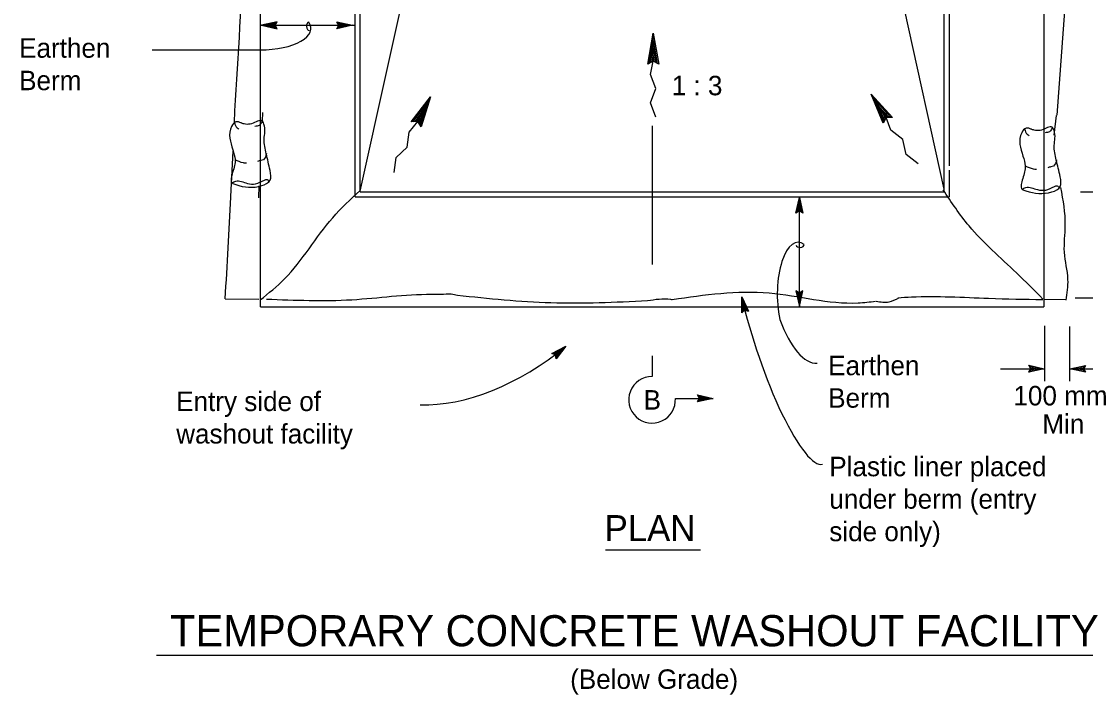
# Model space of a CAD drawing. Extents: x 6707406 to 6714471, y 1868570 to 1872341.
# Drawn here: x 6708832.1 to 6709225.4, y 1868570.1 to 1868819.1 of the extents above; entities that cross this region are included whole.
import ezdxf

# ---------------------------------------------------------------- set-up
doc = ezdxf.new("R2010")
doc.units = 0
for name, color, linetype in [('1 Control', 7, 'Continuous'), ('56 Stg 3 Anno', 7, 'Continuous'), ('57 Undefined', 7, 'Continuous'), ('60 Nongeo Data', 7, 'Continuous')]:
    doc.layers.add(name, color=color, linetype=linetype)

msp = doc.modelspace()

# ---------------------------------------------------------------- linework, layer by layer
at = {"layer": '1 Control'}
for p, q in [((6709098.33, 1868717.18), (6709098.33, 1868717.18)), ((6709098.34, 1868711.27), (6709098.34, 1868711.27)), ((6709100.84, 1868711.84), (6709100.84, 1868711.84)), ((6709204.39, 1868691.86), (6709204.39, 1868691.86)), ((6709204.39, 1868689.29), (6709204.39, 1868689.29)), ((6709210.15, 1868690.57), (6709210.15, 1868690.57)), ((6709219.6, 1868690.57), (6709219.6, 1868690.57)), ((6709225.36, 1868691.85), (6709225.36, 1868691.85)), ((6709225.36, 1868689.28), (6709225.36, 1868689.28))]:
    msp.add_line(p, q, dxfattribs=at)
for points in [[(6709098.34, 1868711.27), (6709098.33, 1868717.18), (6709100.84, 1868711.84), (6709100.46, 1868711.96), (6709098.63, 1868715.87), (6709098.63, 1868711.55), (6709098.91, 1868711.82), (6709098.91, 1868714.59), (6709100.09, 1868712.09), (6709099.71, 1868712.21), (6709099.2, 1868713.29), (6709099.2, 1868712.09), (6709099.43, 1868712.31), (6709100.84, 1868711.84), (6709099.43, 1868712.31)], [(6709204.39, 1868691.86), (6709210.15, 1868690.57), (6709204.39, 1868689.29), (6709204.6, 1868689.63), (6709208.82, 1868690.57), (6709204.6, 1868691.52), (6709204.8, 1868691.18), (6709207.5, 1868690.57), (6709204.8, 1868689.97), (6709205.01, 1868690.31), (6709206.17, 1868690.57), (6709205, 1868690.83), (6709205.16, 1868690.57), (6709204.39, 1868689.29), (6709205.16, 1868690.57)], [(6709225.36, 1868689.28), (6709219.6, 1868690.57), (6709225.36, 1868691.85), (6709225.15, 1868691.51), (6709220.93, 1868690.57), (6709225.15, 1868689.62), (6709224.95, 1868689.96), (6709222.25, 1868690.57), (6709224.95, 1868691.17), (6709224.74, 1868690.83), (6709223.58, 1868690.57), (6709224.75, 1868690.31), (6709224.59, 1868690.57), (6709225.36, 1868691.85), (6709224.59, 1868690.57)]]:
    msp.add_lwpolyline(points, close=True, dxfattribs=at)
for centre, major_axis in [((6708938.43, 1868817.2), (0.09, -1.51)), ((6709119.92, 1868736.43), (1.51, 0.09))]:
    msp.add_ellipse(centre, major_axis=major_axis, ratio=0.650992, start_param=3.141593, end_param=6.283185, dxfattribs=at)
at = {"layer": '56 Stg 3 Anno'}
for p, q in [((6708926.63, 1868818.88), (6708920.87, 1868817.59)), ((6708926.42, 1868818.54), (6708922.19, 1868817.59)), ((6708925.86, 1868817.59), (6708926.63, 1868818.88)), ((6708926.63, 1868818.88), (6708926.63, 1868818.88)), ((6708949.46, 1868817.59), (6708948.69, 1868818.88)), ((6708948.69, 1868818.88), (6708948.69, 1868818.88)), ((6708948.69, 1868818.88), (6708954.45, 1868817.59)), ((6708948.9, 1868818.54), (6708953.13, 1868817.59)), ((6708920.43, 1868817.59), (6708955.21, 1868817.59)), ((6708920.87, 1868817.59), (6708920.87, 1868817.59)), ((6708920.87, 1868817.59), (6708926.63, 1868816.31)), ((6708922.2, 1868817.59), (6708926.4, 1868816.66)), ((6708926.2, 1868818.19), (6708923.52, 1868817.59)), ((6708923.52, 1868817.59), (6708926.23, 1868816.99)), ((6708926.03, 1868817.86), (6708924.85, 1868817.59)), ((6708924.85, 1868817.59), (6708926.01, 1868817.34)), ((6708926.63, 1868816.31), (6708925.86, 1868817.59)), ((6708926.63, 1868816.31), (6708926.63, 1868816.31)), ((6708954.45, 1868817.59), (6708948.69, 1868816.31)), ((6708948.69, 1868816.31), (6708949.46, 1868817.59)), ((6708948.69, 1868816.31), (6708948.69, 1868816.31)), ((6708953.12, 1868817.59), (6708948.92, 1868816.66)), ((6708951.8, 1868817.59), (6708949.09, 1868816.99)), ((6708949.13, 1868818.19), (6708951.8, 1868817.59)), ((6708949.3, 1868817.86), (6708950.48, 1868817.59)), ((6708950.48, 1868817.59), (6708949.32, 1868817.34)), ((6708954.45, 1868817.59), (6708954.45, 1868817.59)), ((6709063.57, 1868803.19), (6709065.61, 1868814.73)), ((6709065.61, 1868814.73), (6709067.65, 1868803.19)), ((6709064.11, 1868803.51), (6709065.61, 1868811.97)), ((6709065.61, 1868811.97), (6709067.11, 1868803.51)), ((6708880.5, 1868808.48), (6708920.43, 1868808.48)), ((6709064.66, 1868803.82), (6709065.61, 1868809.23)), ((6709065.61, 1868809.23), (6709066.56, 1868803.82)), ((6709065.61, 1868804.37), (6709063.57, 1868803.19)), ((6709065.21, 1868804.14), (6709065.61, 1868806.43)), ((6709065.61, 1868806.43), (6709066.01, 1868804.14)), ((6709067.65, 1868803.19), (6709065.61, 1868804.37)), ((6708976.21, 1868781.88), (6708983.33, 1868791.19)), ((6708983.33, 1868791.19), (6708979.83, 1868780)), ((6709150.57, 1868781.35), (6709146.1, 1868792.18)), ((6709146.1, 1868792.18), (6709154.01, 1868783.53)), ((6708976.84, 1868781.91), (6708982.06, 1868788.74)), ((6708982.06, 1868788.74), (6708979.5, 1868780.53)), ((6709150.85, 1868781.9), (6709147.58, 1868789.85)), ((6709147.58, 1868789.85), (6709153.38, 1868783.51)), ((6709151.14, 1868782.46), (6709149.05, 1868787.54)), ((6709149.05, 1868787.54), (6709152.75, 1868783.48)), ((6708977.47, 1868781.94), (6708980.8, 1868786.31)), ((6708978.1, 1868781.97), (6708979.51, 1868783.81)), ((6708979.51, 1868783.81), (6708978.82, 1868781.6)), ((6708980.8, 1868786.31), (6708979.16, 1868781.06)), ((6709151.43, 1868783.03), (6709150.55, 1868785.17)), ((6709150.55, 1868785.17), (6709152.12, 1868783.46)), ((6709151.65, 1868783.44), (6709150.57, 1868781.35)), ((6709154.01, 1868783.53), (6709151.65, 1868783.44)), ((6708978.57, 1868781.99), (6708976.21, 1868781.88)), ((6708979.83, 1868780), (6708978.57, 1868781.99)), ((6709065.3, 1868729.14), (6709065.3, 1868780.38)), ((6709223.56, 1868756.03), (6709282.65, 1868756.03)), ((6709118.34, 1868748.18), (6709119.63, 1868753.94)), ((6709118.69, 1868748.39), (6709119.63, 1868752.62)), ((6709119.63, 1868753.94), (6709119.63, 1868753.94)), ((6709119.63, 1868753.94), (6709120.91, 1868748.18)), ((6709119.63, 1868713.59), (6709119.63, 1868753.09)), ((6709119.63, 1868752.61), (6709120.56, 1868748.41)), ((6709119.63, 1868748.95), (6709118.34, 1868748.18)), ((6709118.34, 1868748.18), (6709118.34, 1868748.18)), ((6709119.03, 1868748.61), (6709119.63, 1868751.29)), ((6709119.36, 1868748.78), (6709119.63, 1868749.96)), ((6709119.63, 1868751.29), (6709120.23, 1868748.58)), ((6709119.63, 1868749.96), (6709119.88, 1868748.8)), ((6709120.91, 1868748.18), (6709119.63, 1868748.95)), ((6709120.91, 1868748.18), (6709120.91, 1868748.18)), ((6709119.63, 1868718.57), (6709118.34, 1868719.34)), ((6709118.34, 1868719.34), (6709118.34, 1868719.34)), ((6709118.34, 1868719.34), (6709119.63, 1868713.58)), ((6709118.69, 1868719.13), (6709119.63, 1868714.91)), ((6709119.03, 1868718.91), (6709119.63, 1868716.23)), ((6709119.36, 1868718.74), (6709119.63, 1868717.56)), ((6709119.63, 1868713.58), (6709120.91, 1868719.34)), ((6709120.91, 1868719.34), (6709119.63, 1868718.57)), ((6709119.63, 1868714.92), (6709120.56, 1868719.12)), ((6709119.63, 1868716.23), (6709120.23, 1868718.95)), ((6709119.63, 1868717.56), (6709119.88, 1868718.72)), ((6709120.91, 1868719.34), (6709120.91, 1868719.34)), ((6709221.6, 1868716.82), (6709283.37, 1868716.82)), ((6709119.63, 1868713.58), (6709119.63, 1868713.58)), ((6709210.27, 1868706.48), (6709210.27, 1868686.06)), ((6709219.46, 1868706.23), (6709219.46, 1868686.06)), ((6709028.12, 1868696.23), (6709033.38, 1868698.91)), ((6709028.5, 1868696.1), (6709032.36, 1868698.07)), ((6709028.89, 1868695.97), (6709031.34, 1868697.22)), ((6709031.34, 1868697.22), (6709029.63, 1868695.03)), ((6709032.35, 1868698.06), (6709029.71, 1868694.66)), ((6709033.38, 1868698.91), (6709029.76, 1868694.25)), ((6709033.38, 1868698.91), (6709033.38, 1868698.91)), ((6709029.53, 1868695.73), (6709028.12, 1868696.23)), ((6709028.12, 1868696.23), (6709028.12, 1868696.23)), ((6709029.24, 1868695.83), (6709030.31, 1868696.38)), ((6709029.76, 1868694.25), (6709029.53, 1868695.73)), ((6709030.31, 1868696.38), (6709029.58, 1868695.44)), ((6709029.76, 1868694.25), (6709029.76, 1868694.25)), ((6709065.18, 1868695.4), (6709065.18, 1868687.67)), ((6709194, 1868690.57), (6709210.15, 1868690.57)), ((6709219.6, 1868690.57), (6709233.02, 1868690.57)), ((6709082.74, 1868679.6), (6709081.97, 1868680.89)), ((6709081.97, 1868680.89), (6709081.97, 1868680.89)), ((6709081.97, 1868680.89), (6709087.74, 1868679.6)), ((6709073.81, 1868679.6), (6709087.74, 1868679.6)), ((6709087.74, 1868679.6), (6709081.98, 1868678.32)), ((6709081.98, 1868678.32), (6709082.74, 1868679.6)), ((6709081.98, 1868678.32), (6709081.98, 1868678.32)), ((6709082.18, 1868680.55), (6709086.41, 1868679.6)), ((6709086.4, 1868679.6), (6709082.2, 1868678.67)), ((6709085.08, 1868679.6), (6709082.37, 1868679)), ((6709082.41, 1868680.2), (6709085.08, 1868679.6)), ((6709082.58, 1868679.87), (6709083.76, 1868679.6)), ((6709083.76, 1868679.6), (6709082.6, 1868679.35)), ((6709087.74, 1868679.6), (6709087.74, 1868679.6))]:
    msp.add_line(p, q, dxfattribs=at)
for points in [[(6709066.56, 1868783.6), (6709064.66, 1868788.88), (6709066.56, 1868794.17), (6709064.66, 1868799.45), (6709065.61, 1868804.37), (6709065.61, 1868814.73)], [(6708969.86, 1868763.1), (6708970.6, 1868768.67), (6708974.72, 1868772.49), (6708975.46, 1868778.06), (6708978.57, 1868781.99), (6708983.33, 1868791.19)], [(6709163.58, 1868766.41), (6709159.15, 1868769.85), (6709157.92, 1868775.33), (6709153.48, 1868778.77), (6709151.65, 1868783.44), (6709146.1, 1868792.18)]]:
    msp.add_lwpolyline(points, dxfattribs=at)
msp.add_arc((6709065.19, 1868679.08), 8.62, 90.1055, 3.4975, dxfattribs=at)
for centre, major_axis, ratio, start_param, end_param in [((6708920.69, 1868816.3), (18.45, 0.17), 0.4237, 4.694534, 6.575355), ((6709119.24, 1868717.91), (-0.1, 19.46), 0.39962, 5.985478, 8.337803), ((6709113.29, 1868700.75), (-14.99, 45.46), 0.209097, 1.133039, 3.129396), ((6709123.13, 1868740.37), (-3.31, 47.75), 0.350985, 2.267971, 3.129396), ((6709008.27, 1868723.75), (-49.44, -37.09), 0.567237, 0.604321, 1.654632)]:
    msp.add_ellipse(centre, major_axis=major_axis, ratio=ratio, start_param=start_param, end_param=end_param, dxfattribs=at)
at = {"layer": '57 Undefined'}
for p, q in [((6709048.02, 1868623.64), (6709083.03, 1868623.64)), ((6708882.08, 1868584.74), (6709251, 1868584.74))]:
    msp.add_line(p, q, dxfattribs=at)
at = {"layer": '60 Nongeo Data'}
for p, q in [((6709218.56, 1868836.41), (6709214.73, 1868784.37)), ((6708910.85, 1868781.61), (6708911.06, 1868785.86)), ((6708921.22, 1868782.08), (6708921.38, 1868785.35)), ((6709214.54, 1868784.28), (6709213.72, 1868777.01)), ((6708909.52, 1868754.31), (6708910.33, 1868771.01)), ((6708919.84, 1868753.8), (6708920.05, 1868758.26)), ((6708957.34, 1868756.03), (6709173.02, 1868756.03)), ((6708955.42, 1868754.11), (6709174.94, 1868754.11)), ((6708907.42, 1868716.46), (6708919.91, 1868716.37)), ((6709210.02, 1868716.31), (6709218.11, 1868716.18)), ((6708920.45, 1868713.46), (6709209.91, 1868713.46))]:
    msp.add_line(p, q, dxfattribs=at)
for points in [[(6708920.45, 1868713.46), (6708920.45, 1869094.08), (6709209.91, 1869094.08), (6709209.91, 1868713.46)], [(6708955.42, 1868754.11), (6708955.42, 1869059.11), (6709174.94, 1869059.11), (6709174.94, 1868765.65)], [(6708957.34, 1868756.03), (6708957.34, 1869057.19), (6709173.02, 1869057.19), (6709173.02, 1868756.03)], [(6708957.38, 1868756.31), (6708987.05, 1868890.2)], [(6709143.66, 1868890.2), (6709172.98, 1868757)], [(6709174.94, 1868764.06), (6709174.94, 1868754.11)]]:
    msp.add_lwpolyline(points, dxfattribs=at)
for points in [[(6708911.04, 1868785.99), (6708914.48, 1868847.99), (6708914.52, 1868848.93)], [(6708913.44, 1868781.48), (6708911.4, 1868781.86), (6708909.81, 1868780.2), (6708910.26, 1868771.52), (6708911.1, 1868767.97), (6708910.19, 1868763.21), (6708910.04, 1868759.29), (6708911.32, 1868758.68), (6708920.93, 1868758.3), (6708924.03, 1868760.27), (6708924.03, 1868763.89), (6708922.6, 1868770.08), (6708921.84, 1868775.52), (6708921.76, 1868781.03), (6708920.7, 1868782.39), (6708918.89, 1868781.86), (6708914.43, 1868781.1), (6708913.21, 1868781.56)], [(6708910.87, 1868781.63), (6708911.85, 1868779.67), (6708912.53, 1868779.22)], [(6708921.23, 1868782.24), (6708920.02, 1868780.58), (6708918.43, 1868780.2)], [(6709205.43, 1868779.15), (6709203.38, 1868779.53), (6709201.79, 1868777.87), (6709202.25, 1868769.19), (6709203.08, 1868765.64), (6709202.17, 1868760.88), (6709202.02, 1868756.96), (6709203.31, 1868756.35), (6709212.92, 1868755.98), (6709216.02, 1868757.94), (6709216.02, 1868761.56), (6709214.58, 1868767.75), (6709213.82, 1868773.19), (6709213.75, 1868778.7), (6709212.69, 1868780.06), (6709210.87, 1868779.53), (6709206.41, 1868778.78), (6709205.2, 1868779.23)], [(6709202.85, 1868779.3), (6709203.84, 1868777.34), (6709204.52, 1868776.89)], [(6709213.22, 1868779.91), (6709212.01, 1868778.25), (6709210.42, 1868777.87)], [(6708911.02, 1868767.97), (6708914.05, 1868766.84), (6708915.26, 1868766.68)], [(6708922.67, 1868770.16), (6708921.54, 1868767.89), (6708920.63, 1868767.59), (6708919.42, 1868767.21)], [(6709214.66, 1868767.83), (6709213.52, 1868765.56), (6709212.61, 1868765.26), (6709211.4, 1868764.88)], [(6709203.01, 1868765.64), (6709206.03, 1868764.51), (6709207.24, 1868764.36)], [(6708909.96, 1868759.29), (6708911.32, 1868759.96), (6708915.64, 1868759.13), (6708918.66, 1868758.98), (6708921.99, 1868760.34), (6708922.9, 1868760.57), (6708923.73, 1868759.59)], [(6708920.4, 1868716.06), (6708929.33, 1868723.79), (6708947.19, 1868746.45), (6708957.25, 1868756.43)], [(6709209.65, 1868716.38), (6709199.89, 1868726.02), (6709182.33, 1868743.4), (6709172.8, 1868756.75)], [(6709201.95, 1868756.96), (6709203.31, 1868757.64), (6709207.62, 1868756.81), (6709210.65, 1868756.66), (6709213.97, 1868758.01), (6709214.88, 1868758.24), (6709215.71, 1868757.26)], [(6709216.18, 1868757.56), (6709217.79, 1868743.66), (6709217.47, 1868733.64), (6709218.76, 1868723.62), (6709218.12, 1868715.91)], [(6708907.43, 1868716.48), (6708909.51, 1868754.03), (6708909.55, 1868754.96)], [(6708922.69, 1868716.35), (6708954.23, 1868716.13), (6708983.7, 1868718.16), (6708987.22, 1868718.11)], [(6708987.22, 1868718.11), (6708990.96, 1868718.24), (6708993.28, 1868717.81)], [(6708993.28, 1868717.81), (6709027.81, 1868715.05), (6709063.48, 1868715.77)], [(6709063.48, 1868715.77), (6709072.06, 1868716.3), (6709072.66, 1868716.2)], [(6709072.66, 1868716.2), (6709108.46, 1868718.65), (6709141.34, 1868714.95), (6709147.79, 1868715.58)], [(6709148.04, 1868715.58), (6709152.77, 1868715.33), (6709156.34, 1868716.84)], [(6709155.99, 1868716.83), (6709161.07, 1868717.14), (6709189.58, 1868716.65), (6709209.56, 1868716.17)]]:
    msp.add_spline(points, degree=3, dxfattribs=at)

# ---------------------------------------------------------------- texts
at = {"layer": '57 Undefined'}
for s, height, p in [('Earthen', 7.2, (6708831.3, 1868805.59)), ('Berm', 7.2, (6708831.3, 1868793.59)), ('Earthen', 7.2, (6709130.28, 1868688.19)), ('Entry side of', 7.2002, (6708889.34, 1868674.94)), ('B', 7.21, (6709062.06, 1868675.48)), ('Berm', 7.2, (6709130.28, 1868676.19)), ('100 mm', 7.2, (6709198.74, 1868677.03)), ('Min', 7.2, (6709209.42, 1868666.59)), ('washout facility', 7.2002, (6708889.34, 1868662.94)), ('Plastic liner placed ', 7.2002, (6709130.69, 1868650.84)), ('under berm (entry ', 7.2002, (6709130.69, 1868638.84)), ('PLAN', 9.6, (6709047.66, 1868626.86)), ('side only)', 7.2, (6709130.69, 1868626.83)), ('TEMPORARY CONCRETE WASHOUT FACILITY', 11.5203, (6708887.03, 1868587.96)), ('(Below Grade)', 7.2002, (6709034.93, 1868572.22))]:
    msp.add_text(s, height=height, dxfattribs=at).set_placement(p)
msp.add_text('1 : 3', height=7.2, rotation=359.9387, dxfattribs=at).set_placement((6709072.45, 1868791.73))

doc.saveas('drawing.dxf')
